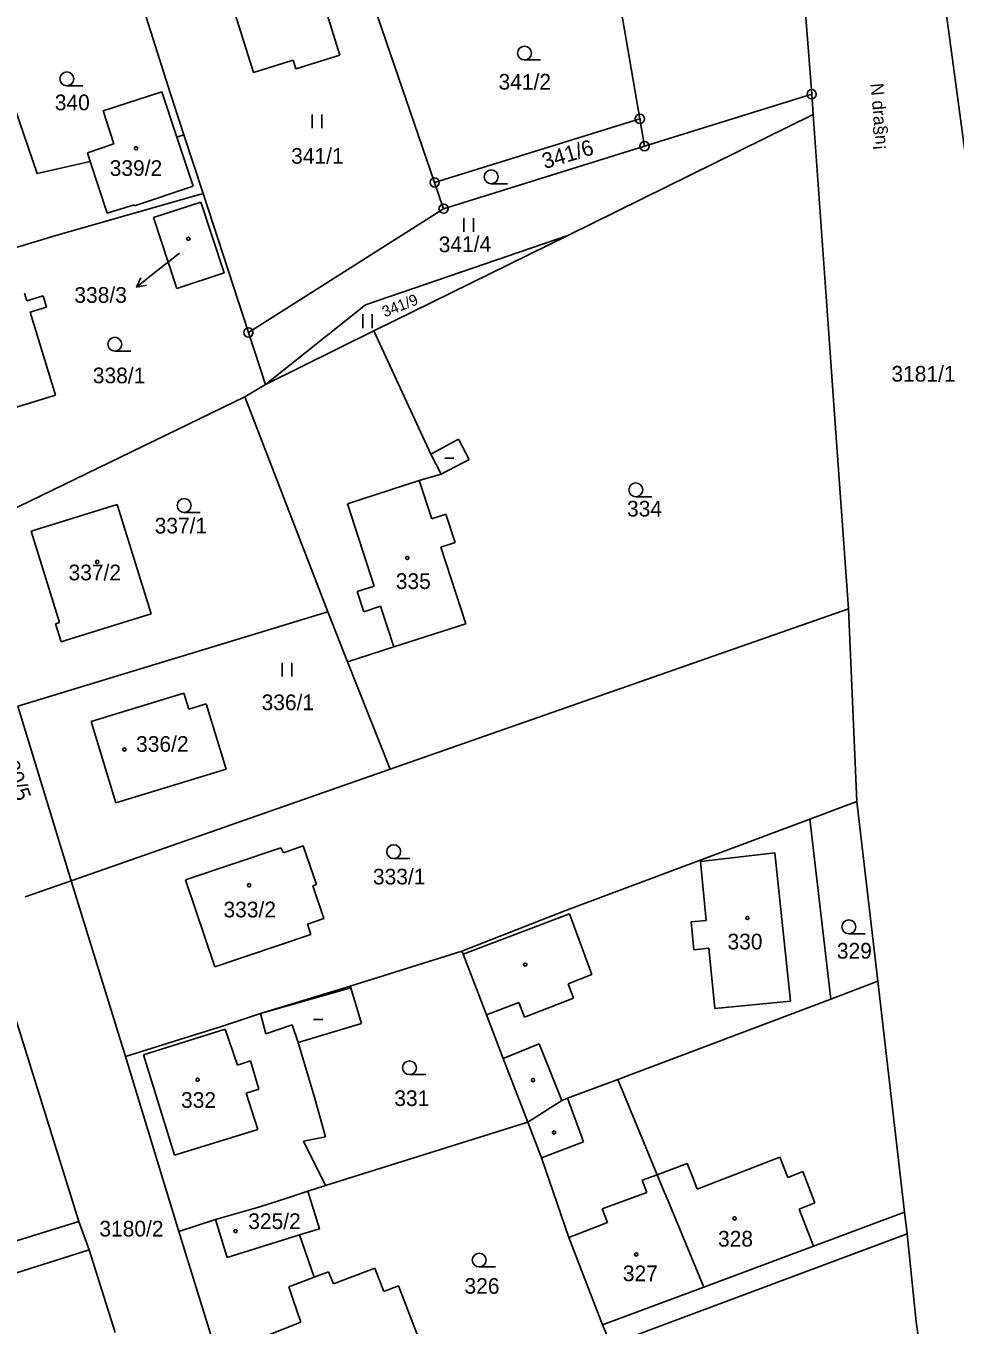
# Model space of a CAD drawing. Extents: x -736345 to -729997, y -1130177 to -1122501.
# Drawn here: x -733544.4 to -733443.8, y -1126639.6 to -1126498.8 of the extents above; entities that cross this region are included whole.
import ezdxf

# ---------------------------------------------------------------- set-up
doc = ezdxf.new("R2010")
doc.units = 0
for name, color, linetype in [('Vrstva 1', 7, 'Continuous'), ('Vrstva 15', 7, 'Continuous'), ('Vrstva 16', 7, 'Continuous'), ('Vrstva 18', 7, 'Continuous'), ('Vrstva 19', 7, 'Continuous'), ('Vrstva 25', 7, 'Continuous'), ('Vrstva 4', 7, 'Continuous')]:
    doc.layers.add(name, color=color, linetype=linetype)

msp = doc.modelspace()

# ---------------------------------------------------------------- linework, layer by layer
at = {"layer": 'Vrstva 1'}
for points in [[(-733463.04, -1126458.66), (-733459.32, -1126506.2)], [(-733484.01, -1126473.61), (-733477.94, -1126508.87)], [(-733500.17, -1126515.76), (-733511.6, -1126482.44)], [(-733534.04, -1126489.63), (-733528.79, -1126506.14)], [(-733441.21, -1126523.58), (-733445.8, -1126489.58)], [(-733510.43, -1126501.98), (-733513.67, -1126491.6)], [(-733550.09, -1126494.79), (-733543.24, -1126514.79)], [(-733522.75, -1126494.38), (-733519.81, -1126503.83)], [(-733515.21, -1126503.45), (-733510.43, -1126501.98)], [(-733519.81, -1126503.83), (-733515.5, -1126502.5)], [(-733515.5, -1126502.5), (-733515.21, -1126503.45)], [(-733529.73, -1126505.93), (-733536.1, -1126508.01)], [(-733528.09, -1126510.84), (-733529.73, -1126505.93)], [(-733527.34, -1126510.59), (-733528.79, -1126506.14)], [(-733477.43, -1126511.83), (-733459.32, -1126506.2)], [(-733459.32, -1126506.2), (-733459.15, -1126508.39)], [(-733536.1, -1126508.01), (-733534.92, -1126511.56)], [(-733500.17, -1126515.76), (-733477.94, -1126508.87)], [(-733459.15, -1126508.39), (-733485.73, -1126521.49)], [(-733477.43, -1126511.83), (-733477.94, -1126508.87)], [(-733459.15, -1126508.39), (-733457.35, -1126533.67)], [(-733534.92, -1126511.56), (-733537.8, -1126512.54)], [(-733528.09, -1126510.84), (-733527.34, -1126510.59)], [(-733526.32, -1126516.16), (-733528.09, -1126510.84)], [(-733525.26, -1126516.95), (-733527.34, -1126510.59)], [(-733477.43, -1126511.83), (-733499.2, -1126518.6)], [(-733537.8, -1126512.54), (-733537.49, -1126513.48)], [(-733543.24, -1126514.79), (-733537.49, -1126513.48)], [(-733537.49, -1126513.48), (-733535.64, -1126519.07)], [(-733532.68, -1126518.29), (-733526.32, -1126516.16)], [(-733500.17, -1126515.76), (-733499.2, -1126518.6)], [(-733540.96, -1126521.43), (-733525.26, -1126516.95)], [(-733525.26, -1126516.95), (-733520.35, -1126532.01)], [(-733535.64, -1126519.07), (-733532.72, -1126518.17)], [(-733532.72, -1126518.17), (-733532.68, -1126518.29)], [(-733525.51, -1126517.89), (-733530.62, -1126519.57)], [(-733522.99, -1126525.57), (-733525.51, -1126517.89)], [(-733520.35, -1126532.01), (-733499.2, -1126518.6)], [(-733528.1, -1126527.25), (-733530.62, -1126519.57)], [(-733559.56, -1126527.04), (-733540.96, -1126521.43)], [(-733485.73, -1126521.49), (-733507.68, -1126529.03)], [(-733485.73, -1126521.49), (-733506.75, -1126531.85)], [(-733528.1, -1126527.25), (-733522.99, -1126525.57)], [(-733544.37, -1126528.58), (-733544.62, -1126527.77)], [(-733542.59, -1126528.03), (-733544.37, -1126528.58)], [(-733542.21, -1126529.29), (-733542.59, -1126528.03)], [(-733543.99, -1126529.83), (-733542.21, -1126529.29)], [(-733541.25, -1126538.82), (-733543.99, -1126529.83)], [(-733518.51, -1126537.65), (-733507.68, -1126529.03)], [(-733520.35, -1126532.01), (-733518.51, -1126537.65)], [(-733506.75, -1126531.85), (-733518.51, -1126537.65)], [(-733506.75, -1126531.85), (-733500.6, -1126545.2)], [(-733457.35, -1126533.67), (-733456.91, -1126539.85)], [(-733520.75, -1126539), (-733518.51, -1126537.65)], [(-733551.35, -1126553.85), (-733520.75, -1126539)], [(-733550.82, -1126541.74), (-733541.25, -1126538.82)], [(-733520.75, -1126539), (-733511.74, -1126562.29)], [(-733456.91, -1126539.85), (-733455.34, -1126561.97)], [(-733500.6, -1126545.2), (-733497.59, -1126543.59)], [(-733497.59, -1126543.59), (-733496.42, -1126545.78)], [(-733496.42, -1126545.78), (-733499.45, -1126547.35)], [(-733499.45, -1126547.35), (-733501.85, -1126548.04)], [(-733501.85, -1126548.04), (-733500.49, -1126552.2)], [(-733543.89, -1126553.54), (-733534.56, -1126550.65)], [(-733534.56, -1126550.65), (-733530.87, -1126562.5)], [(-733500.49, -1126552.2), (-733498.95, -1126551.7)], [(-733498.95, -1126551.7), (-733497.95, -1126554.78)], [(-733540.82, -1126563.43), (-733543.89, -1126553.54)], [(-733497.95, -1126554.78), (-733499.49, -1126555.28)], [(-733499.49, -1126555.28), (-733496.78, -1126563.59)], [(-733545.34, -1126572.51), (-733511.74, -1126562.29)], [(-733530.87, -1126562.5), (-733540.21, -1126565.4)], [(-733509.6, -1126567.69), (-733511.74, -1126562.29)], [(-733504.98, -1126579.32), (-733455.34, -1126561.97)], [(-733455.34, -1126561.97), (-733454.43, -1126582.85)], [(-733541.26, -1126563.57), (-733540.82, -1126563.43)], [(-733540.65, -1126565.54), (-733541.26, -1126563.57)], [(-733496.78, -1126563.59), (-733504.6, -1126566.09)], [(-733540.21, -1126565.4), (-733540.65, -1126565.54)], [(-733504.6, -1126566.09), (-733509.6, -1126567.69)], [(-733504.98, -1126579.32), (-733509.6, -1126567.69)], [(-733527.35, -1126571.1), (-733537.4, -1126574.17)], [(-733526.82, -1126572.83), (-733527.35, -1126571.1)], [(-733524.91, -1126572.24), (-733526.82, -1126572.83)], [(-733522.75, -1126579.33), (-733524.91, -1126572.24)], [(-733539.57, -1126591.42), (-733545.34, -1126572.51)], [(-733537.4, -1126574.17), (-733534.72, -1126582.98)], [(-733539.57, -1126591.42), (-733504.98, -1126579.32)], [(-733534.72, -1126582.98), (-733522.75, -1126579.33)], [(-733459.53, -1126584.76), (-733454.43, -1126582.85)], [(-733454.43, -1126582.85), (-733452.16, -1126602.32)], [(-733486.06, -1126594.69), (-733459.53, -1126584.76)], [(-733459.53, -1126584.76), (-733457.26, -1126604.24)], [(-733516.84, -1126587.85), (-733527.15, -1126591.32)], [(-733516.56, -1126588.38), (-733516.84, -1126587.85)], [(-733514.4, -1126587.65), (-733516.56, -1126588.38)], [(-733512.99, -1126591.83), (-733514.4, -1126587.65)], [(-733544.53, -1126593.16), (-733539.57, -1126591.42)], [(-733539.57, -1126591.42), (-733533.65, -1126610.47)], [(-733527.15, -1126591.32), (-733523.98, -1126600.76)], [(-733513.37, -1126591.96), (-733512.99, -1126591.83)], [(-733512.17, -1126595.52), (-733513.37, -1126591.96)], [(-733497.21, -1126599.06), (-733486.06, -1126594.69)], [(-733538.73, -1126628.34), (-733549.06, -1126595.31)], [(-733513.96, -1126596.12), (-733512.17, -1126595.52)], [(-733513.59, -1126597.26), (-733513.96, -1126596.12)], [(-733523.98, -1126600.76), (-733513.59, -1126597.26)], [(-733509.32, -1126602.84), (-733497.21, -1126599.06)], [(-733497.09, -1126599.38), (-733497.21, -1126599.06)], [(-733494.56, -1126605.95), (-733497.09, -1126599.38)], [(-733519.03, -1126605.82), (-733509.32, -1126602.84)], [(-733509.26, -1126603.03), (-733509.32, -1126602.84)], [(-733508.1, -1126606.89), (-733509.26, -1126603.03)], [(-733452.16, -1126602.32), (-733457.26, -1126604.24)], [(-733452.16, -1126602.32), (-733449.25, -1126627.32)], [(-733457.26, -1126604.24), (-733480.33, -1126612.94)], [(-733523.15, -1126607.17), (-733519.03, -1126605.82)], [(-733492.74, -1126610.67), (-733494.56, -1126605.95)], [(-733533.65, -1126610.47), (-733523.15, -1126607.17)], [(-733514.96, -1126608.94), (-733508.1, -1126606.89)], [(-733514.96, -1126608.94), (-733513.14, -1126615)], [(-733530.22, -1126621.73), (-733533.65, -1126610.47)], [(-733490.07, -1126617.59), (-733492.74, -1126610.67)], [(-733480.33, -1126612.94), (-733485.79, -1126614.99)], [(-733480.33, -1126612.94), (-733476.06, -1126623.27)], [(-733513.14, -1126615), (-733512.01, -1126619.16)], [(-733486.38, -1126615.23), (-733490.07, -1126617.59)], [(-733485.79, -1126614.99), (-733486.38, -1126615.23)], [(-733490.07, -1126617.59), (-733511.98, -1126624.44)], [(-733488.6, -1126621.46), (-733490.07, -1126617.59)], [(-733512.01, -1126619.16), (-733514.37, -1126619.63)], [(-733514.37, -1126619.63), (-733511.98, -1126624.44)], [(-733527.88, -1126629.41), (-733530.22, -1126621.73)], [(-733485.64, -1126630.07), (-733488.6, -1126621.46)], [(-733511.98, -1126624.44), (-733513.91, -1126625.07)], [(-733476.06, -1126623.27), (-733475.47, -1126624.69)], [(-733516.18, -1126625.8), (-733519.1, -1126626.75)], [(-733513.91, -1126625.07), (-733516.18, -1126625.8)], [(-733513.91, -1126625.07), (-733512.66, -1126629.12), (-733514.8, -1126629.79)], [(-733475.47, -1126624.69), (-733474.92, -1126626.03)], [(-733519.1, -1126626.75), (-733523.92, -1126628.14)], [(-733474.92, -1126626.03), (-733471.02, -1126635.45)], [(-733449.25, -1126627.32), (-733459.11, -1126631)], [(-733449.25, -1126627.32), (-733448.98, -1126629.67)], [(-733538.73, -1126628.34), (-733557.07, -1126634.01)], [(-733537.61, -1126631.43), (-733538.73, -1126628.34)], [(-733523.92, -1126628.14), (-733527.88, -1126629.41)], [(-733514.8, -1126629.79), (-733522.65, -1126632.23), (-733523.92, -1126628.14)], [(-733527.88, -1126629.41), (-733523.05, -1126645.08)], [(-733514.8, -1126629.79), (-733513.21, -1126634.38)], [(-733481.99, -1126639.55), (-733485.64, -1126630.07)], [(-733448.98, -1126629.67), (-733481.09, -1126641.68)], [(-733448.98, -1126629.67), (-733447.99, -1126639.23)], [(-733537.61, -1126631.43), (-733556.36, -1126637.34)], [(-733534.77, -1126640.37), (-733537.61, -1126631.43)], [(-733471.02, -1126635.45), (-733459.11, -1126631)], [(-733511.67, -1126633.8), (-733513.21, -1126634.38)], [(-733511.13, -1126635.08), (-733511.67, -1126633.8)], [(-733506.65, -1126633.4), (-733511.13, -1126635.08)], [(-733505.69, -1126635.94), (-733506.65, -1126633.4)], [(-733504.07, -1126635.33), (-733505.69, -1126635.94)], [(-733500.61, -1126644.36), (-733504.07, -1126635.33)], [(-733481.28, -1126641.23), (-733481.99, -1126639.55)], [(-733447.99, -1126639.23), (-733447.64, -1126641.69)]]:
    msp.add_lwpolyline(points, dxfattribs=at)
at = {"layer": 'Vrstva 16'}
msp.add_lwpolyline([(-733527.81, -1126523.41), (-733530.12, -1126525.24)], dxfattribs=at)
at = {"layer": 'Vrstva 25'}
for points in [[(-733490.44, -1126502.49), (-733488.69, -1126502.49)], [(-733540.03, -1126505.29), (-733538.28, -1126505.29)], [(-733513.427, -1126509.885), (-733513.427, -1126508.385)], [(-733512.393, -1126509.885), (-733512.393, -1126508.385)], [(-733494.04, -1126515.9), (-733492.29, -1126515.9)], [(-733496.997, -1126521.125), (-733496.997, -1126519.625)], [(-733495.963, -1126521.125), (-733495.963, -1126519.625)], [(-733530.12, -1126525.24), (-733532.474, -1126527.099)], [(-733531.379, -1126526.871), (-733532.474, -1126527.099), (-733531.999, -1126526.087)], [(-733507.957, -1126531.535), (-733507.957, -1126530.035)], [(-733506.923, -1126531.535), (-733506.923, -1126530.035)], [(-733534.83, -1126534.04), (-733533.08, -1126534.04)], [(-733499.08, -1126545.64), (-733498.08, -1126545.64)], [(-733478.38, -1126549.81), (-733476.63, -1126549.81)], [(-733527.31, -1126551.51), (-733525.56, -1126551.51)], [(-733516.677, -1126569.305), (-733516.677, -1126567.805)], [(-733515.643, -1126569.305), (-733515.643, -1126567.805)], [(-733504.61, -1126589.02), (-733502.86, -1126589.02)], [(-733455.29, -1126597.16), (-733453.54, -1126597.16)], [(-733513.29, -1126606.47), (-733512.29, -1126606.47)], [(-733502.89, -1126612.43), (-733501.14, -1126612.43)], [(-733495.34, -1126633.27), (-733493.59, -1126633.27)]]:
    msp.add_lwpolyline(points, dxfattribs=at)
for centre, radius in [((-733490.44, -1126501.74), 0.75), ((-733540.03, -1126504.54), 0.75), ((-733459.32, -1126506.2), 0.5), ((-733459.32, -1126506.2), 0.032), ((-733477.94, -1126508.87), 0.5), ((-733477.94, -1126508.87), 0.032), ((-733532.52, -1126512.05), 0.175), ((-733477.43, -1126511.83), 0.5), ((-733477.43, -1126511.83), 0.032), ((-733494.04, -1126515.15), 0.75), ((-733500.17, -1126515.76), 0.5), ((-733500.17, -1126515.76), 0.032), ((-733499.2, -1126518.6), 0.5), ((-733499.2, -1126518.6), 0.032), ((-733526.85, -1126521.87), 0.175), ((-733520.35, -1126532.01), 0.5), ((-733534.83, -1126533.29), 0.75), ((-733520.35, -1126532.01), 0.032), ((-733478.38, -1126549.06), 0.75), ((-733527.31, -1126550.76), 0.75), ((-733536.73, -1126556.87), 0.175), ((-733503.13, -1126556.45), 0.175), ((-733533.78, -1126577.2), 0.175), ((-733504.61, -1126588.27), 0.75), ((-733520.28, -1126591.91), 0.175), ((-733466.29, -1126595.46), 0.175), ((-733455.29, -1126596.41), 0.75), ((-733490.36, -1126600.51), 0.175), ((-733502.89, -1126611.68), 0.75), ((-733525.85, -1126612.98), 0.175), ((-733489.51, -1126613.02), 0.175), ((-733487.23, -1126618.7), 0.175), ((-733467.67, -1126628.01), 0.175), ((-733521.74, -1126629.39), 0.175), ((-733495.34, -1126632.52), 0.75), ((-733478.33, -1126631.92), 0.175)]:
    msp.add_circle(centre, radius, dxfattribs=at)
at = {"layer": 'Vrstva 4'}
for points in [[(-733500.6, -1126545.2), (-733499.45, -1126547.35)], [(-733509.63, -1126550.57), (-733501.85, -1126548.04)], [(-733506.73, -1126559.5), (-733509.63, -1126550.57)], [(-733508.56, -1126560.09), (-733506.73, -1126559.5)], [(-733507.85, -1126562.27), (-733508.56, -1126560.09)], [(-733506.03, -1126561.68), (-733507.85, -1126562.27)], [(-733504.6, -1126566.09), (-733506.03, -1126561.68)], [(-733463.31, -1126588.4), (-733471.38, -1126589.35)], [(-733471.38, -1126589.35), (-733470.74, -1126595.73)], [(-733461.63, -1126604.48), (-733463.31, -1126588.4)], [(-733485.57, -1126595), (-733497.09, -1126599.38)], [(-733483.13, -1126601.58), (-733485.57, -1126595)], [(-733470.74, -1126595.73), (-733472.39, -1126595.89)], [(-733472.39, -1126595.89), (-733472.09, -1126598.89)], [(-733472.09, -1126598.89), (-733470.47, -1126598.72)], [(-733470.47, -1126598.72), (-733469.81, -1126605.28)], [(-733485.71, -1126602.58), (-733483.13, -1126601.58)], [(-733509.26, -1126603.03), (-733519.03, -1126605.82)], [(-733485.11, -1126604.13), (-733485.71, -1126602.58)], [(-733494.56, -1126605.95), (-733491.06, -1126604.6)], [(-733491.06, -1126604.6), (-733490.45, -1126606.2)], [(-733490.45, -1126606.2), (-733485.11, -1126604.13)], [(-733469.81, -1126605.28), (-733461.63, -1126604.48)], [(-733519.03, -1126605.82), (-733518.47, -1126608.01)], [(-733531.72, -1126610.28), (-733522.86, -1126607.5)], [(-733522.86, -1126607.5), (-733521.54, -1126611.4)], [(-733518.47, -1126608.01), (-733515.61, -1126607.03)], [(-733515.61, -1126607.03), (-733514.96, -1126608.94)], [(-733492.74, -1126610.67), (-733488.83, -1126609.09)], [(-733488.83, -1126609.09), (-733486.38, -1126615.23)], [(-733528.36, -1126621.16), (-733531.72, -1126610.28)], [(-733521.54, -1126611.4), (-733520.14, -1126610.92)], [(-733520.14, -1126610.92), (-733519.22, -1126614)], [(-733519.22, -1126614), (-733520.6, -1126614.44)], [(-733520.6, -1126614.44), (-733519.34, -1126618.38)], [(-733485.79, -1126614.99), (-733484.03, -1126619.7)], [(-733519.34, -1126618.38), (-733528.36, -1126621.16)], [(-733484.03, -1126619.7), (-733488.6, -1126621.46)], [(-733462.76, -1126621.36), (-733471.71, -1126624.85)], [(-733461.9, -1126623.57), (-733462.76, -1126621.36)], [(-733472.8, -1126622.06), (-733476.06, -1126623.27)], [(-733472.21, -1126623.56), (-733472.8, -1126622.06)], [(-733460.29, -1126622.94), (-733461.9, -1126623.57)], [(-733458.97, -1126626.33), (-733460.29, -1126622.94)], [(-733476.06, -1126623.27), (-733477.67, -1126623.87)], [(-733477.67, -1126623.87), (-733477.18, -1126625.19)], [(-733471.71, -1126624.85), (-733472.21, -1126623.56)], [(-733477.18, -1126625.19), (-733482.03, -1126626.96)], [(-733482.03, -1126626.96), (-733481.45, -1126628.44)], [(-733460.67, -1126626.99), (-733458.97, -1126626.33)], [(-733459.11, -1126631), (-733460.67, -1126626.99)], [(-733481.45, -1126628.44), (-733485.64, -1126630.07)], [(-733513.21, -1126634.38), (-733515.98, -1126635.43)], [(-733515.98, -1126635.43), (-733515.53, -1126636.73)], [(-733471.02, -1126635.45), (-733481.99, -1126639.55)], [(-733515.53, -1126636.73), (-733514.67, -1126639.25)], [(-733514.67, -1126639.25), (-733520.05, -1126641.37)]]:
    msp.add_lwpolyline(points, dxfattribs=at)

# ---------------------------------------------------------------- texts
at = {"layer": 'Vrstva 15'}
msp.add_text('N\xa0dra§n¡', height=1.4, rotation=274.90219, dxfattribs=at).set_placement((-733452.954, -1126505.062))
at = {"layer": 'Vrstva 16'}
msp.add_text('338/3', height=1.7, dxfattribs=at).set_placement((-733539.206, -1126528.8))
at = {"layer": 'Vrstva 18'}
for s, p in [('341/2', (-733493.25, -1126505.7)), ('340', (-733541.33, -1126507.94)), ('341/1', (-733515.72, -1126513.73)), ('338/1', (-733537.21, -1126537.52)), ('3181/1', (-733450.68, -1126537.34)), ('334', (-733479.33, -1126551.96)), ('337/1', (-733530.51, -1126553.79)), ('336/1', (-733518.92, -1126572.94)), ('333/1', (-733506.86, -1126591.82)), ('329', (-733456.59, -1126599.86)), ('331', (-733504.54, -1126615.83)), ('3180/2', (-733536.5, -1126629.97)), ('326', (-733496.94, -1126636.17))]:
    msp.add_text(s, height=1.7, dxfattribs=at).set_placement(p)
for s, height, rotation, p in [('341/6', 1.7, 16.70013, (-733488.246, -1126514.321)), ('341/4', 1.7, 0.60001, (-733499.723, -1126523.328)), ('341/9', 1.2, 21.60017, (-733505.578, -1126530.391)), ('3180/5', 1.7, 289.5023, (-733547.765, -1126576.351))]:
    msp.add_text(s, height=height, rotation=rotation, dxfattribs=at).set_placement(p)
at = {"layer": 'Vrstva 19'}
for s, height, p in [('339/2', 1.7, (-733535.38, -1126515.05)), ('338/3', 0.1, (-733527.61, -1126523.21)), ('337/2', 1.7, (-733539.84, -1126558.87)), ('335', 1.7, (-733504.38, -1126559.81)), ('336/2', 1.7, (-733532.52, -1126577.45)), ('333/2', 1.7, (-733523.05, -1126595.39)), ('330', 1.7, (-733468.44, -1126598.86)), ('332', 1.7, (-733527.65, -1126616.03)), ('325/2', 1.7, (-733520.368, -1126629.16)), ('328', 1.7, (-733469.47, -1126631.06)), ('327', 1.7, (-733479.78, -1126634.81))]:
    msp.add_text(s, height=height, dxfattribs=at).set_placement(p)

doc.saveas('drawing.dxf')
